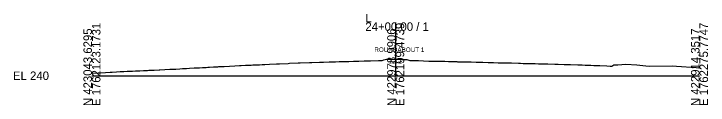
# Model space of a CAD drawing. Extents: x -26 to 3203, y -11010 to 4024.
# Drawn here: x -25.7 to 202.8, y -2009.7 to -1979.6 of the extents above; entities that cross this region are included whole.
import ezdxf

# ---------------------------------------------------------------- set-up
doc = ezdxf.new("R2010")
doc.units = 0
for name, color, linetype in [('Default', 7, 'Continuous'), ('Exist Cross Section Cell', 7, 'Continuous'), ('Exist XS Center Line Elevation Label', 7, 'Continuous'), ('Exist XS Ground Line', 7, 'Continuous'), ('Prop XS SE Text', 7, 'Continuous')]:
    doc.layers.add(name, color=color, linetype=linetype)

msp = doc.modelspace()

# ---------------------------------------------------------------- linework, layer by layer
at = {"layer": 'Exist Cross Section Cell'}
for p, q in [((100, -2000), (100, -1982.38)), ((0, -2000), (100, -2000)), ((100, -2000), (200, -2000))]:
    msp.add_line(p, q, dxfattribs=at)
at = {"layer": 'Exist XS Ground Line'}
msp.add_lwpolyline([(0, -1999.13), (2, -1999.02), (2.67, -1998.99), (2.8, -1998.98), (4.5, -1998.91), (5.96, -1998.82), (6.28, -1998.8), (6.67, -1998.78), (8.05, -1998.72), (9.24, -1998.64), (9.83, -1998.61), (10.53, -1998.57), (11.6, -1998.52), (12.5, -1998.47), (13.37, -1998.43), (14.39, -1998.38), (15.15, -1998.35), (15.79, -1998.32), (16.93, -1998.27), (18.27, -1998.21), (18.7, -1998.19), (19.07, -1998.17), (20.47, -1998.11), (22.14, -1998.02), (22.25, -1998.01), (22.34, -1998.01), (24.02, -1997.95), (25.62, -1997.87), (26.01, -1997.85), (27.57, -1997.77), (28.9, -1997.68), (29.86, -1997.63), (31.11, -1997.56), (32.17, -1997.51), (33.7, -1997.43), (34.65, -1997.38), (35.45, -1997.34), (36.42, -1997.29), (37.57, -1997.22), (38.2, -1997.19), (38.73, -1997.16), (39.97, -1997.09), (41.44, -1997), (41.75, -1996.99), (42.01, -1996.97), (43.52, -1996.89), (45.29, -1996.8), (45.29, -1996.8), (45.3, -1996.8), (47.07, -1996.71), (48.57, -1996.65), (49.16, -1996.62), (50.6, -1996.55), (51.88, -1996.49), (52.38, -1996.47), (52.99, -1996.44), (54.09, -1996.38), (55.16, -1996.34), (56, -1996.3), (56.94, -1996.25), (58.41, -1996.17), (60.78, -1996.07), (61.71, -1996.03), (64.63, -1995.9), (65.04, -1995.88), (67.9, -1995.75), (68.3, -1995.73), (68.43, -1995.72), (68.52, -1995.72), (71.61, -1995.63), (71.99, -1995.62), (72.42, -1995.6), (74.86, -1995.53), (75.52, -1995.51), (76.27, -1995.49), (78.09, -1995.45), (79.44, -1995.4), (79.92, -1995.38), (80, -1995.38), (80.22, -1995.37), (81.34, -1995.33), (82.54, -1995.3), (83.97, -1995.25), (84.61, -1995.24), (86.05, -1995.2), (87.82, -1995.17), (87.9, -1995.17), (89.57, -1995.13), (91.15, -1995.09), (91.67, -1995.08), (94.33, -1995.01), (95.09, -1994.97), (95.57, -1994.93), (96.07, -1994.8), (96.92, -1994.58), (98.21, -1994.57), (102.15, -1994.6), (103.49, -1994.62), (103.51, -1994.62), (103.67, -1994.67), (104.61, -1994.96), (104.7, -1994.96), (107.24, -1994.99), (107.52, -1995), (109.18, -1995.08), (110.93, -1995.14), (111, -1995.14), (111.09, -1995.14), (114, -1995.19), (114.92, -1995.21), (116.22, -1995.23), (117.34, -1995.27), (118.03, -1995.3), (118.8, -1995.31), (120.07, -1995.34), (120.39, -1995.35), (121.08, -1995.36), (122.64, -1995.39), (123.58, -1995.41), (124.72, -1995.43), (124.82, -1995.43), (126.5, -1995.47), (126.79, -1995.48), (127.06, -1995.49), (128.68, -1995.52), (130.4, -1995.57), (130.41, -1995.57), (132.2, -1995.63), (133.76, -1995.68), (134.02, -1995.69), (134.3, -1995.69), (135.78, -1995.73), (137.12, -1995.76), (137.6, -1995.77), (138.15, -1995.78), (140.42, -1995.85), (141.13, -1995.87), (141.99, -1995.9), (143.66, -1995.93), (144.66, -1995.95), (145.95, -1995.98), (146.99, -1996.01), (149.8, -1996.11), (149.94, -1996.11), (150.09, -1996.11), (152.4, -1996.18), (153.38, -1996.21), (153.44, -1996.21), (153.52, -1996.21), (155.46, -1996.26), (156.8, -1996.29), (157.5, -1996.31), (159.97, -1996.38), (160.59, -1996.4), (161.33, -1996.42), (162.41, -1996.46), (163.37, -1996.5), (164.21, -1996.53), (165.22, -1996.57), (166.46, -1996.62), (166.82, -1996.64), (167.2, -1996.65), (169.47, -1996.75), (170.65, -1996.8), (171.16, -1996.82), (171.51, -1996.58), (171.82, -1996.38), (172.05, -1996.38), (173.17, -1996.36), (175.79, -1996.19), (179.33, -1996.41), (182.34, -1996.74), (183.43, -1996.78), (191.26, -1996.72), (192.43, -1996.81), (198.92, -1997.29), (200, -1997.38)], dxfattribs=at)
msp.add_lwpolyline([(0, -1999.13), (2, -1999.02), (2.67, -1998.99), (2.8, -1998.98), (4.5, -1998.91), (5.96, -1998.82), (6.28, -1998.8), (6.67, -1998.78), (8.05, -1998.72), (9.24, -1998.64), (9.83, -1998.61), (10.53, -1998.57), (11.6, -1998.52), (12.5, -1998.47), (13.37, -1998.43), (14.39, -1998.38), (15.15, -1998.35), (15.79, -1998.32), (16.93, -1998.27), (18.27, -1998.21), (18.7, -1998.19), (19.07, -1998.17), (20.47, -1998.11), (22.14, -1998.02), (22.25, -1998.01), (22.34, -1998.01), (24.02, -1997.95), (25.62, -1997.87), (26.01, -1997.85), (27.57, -1997.77), (28.9, -1997.68), (29.86, -1997.63), (31.11, -1997.56), (32.17, -1997.51), (33.7, -1997.43), (34.65, -1997.38), (35.45, -1997.34), (36.42, -1997.29), (37.57, -1997.22), (38.2, -1997.19), (38.73, -1997.16), (39.97, -1997.09), (41.44, -1997), (41.75, -1996.99), (42.01, -1996.97), (43.52, -1996.89), (45.29, -1996.8), (45.29, -1996.8), (45.3, -1996.8), (47.07, -1996.71), (48.57, -1996.65), (49.16, -1996.62), (50.6, -1996.55), (51.88, -1996.49), (52.38, -1996.47), (52.99, -1996.44), (54.09, -1996.38), (55.16, -1996.34), (56, -1996.3), (56.94, -1996.25), (58.41, -1996.17), (60.78, -1996.07), (61.71, -1996.03), (64.63, -1995.9), (65.04, -1995.88), (67.9, -1995.75), (68.3, -1995.73), (68.43, -1995.72), (68.52, -1995.72), (71.61, -1995.63), (71.99, -1995.62), (72.42, -1995.6), (74.86, -1995.53), (75.52, -1995.51), (76.27, -1995.49), (78.09, -1995.45), (79.44, -1995.4), (79.92, -1995.38), (80, -1995.38), (80.22, -1995.37), (81.34, -1995.33), (82.54, -1995.3), (83.97, -1995.25), (84.61, -1995.24), (86.05, -1995.2), (87.82, -1995.17), (87.9, -1995.17), (89.57, -1995.13), (91.15, -1995.09), (91.67, -1995.08), (94.33, -1995.01), (95.09, -1994.97), (95.57, -1994.93), (96.07, -1994.8), (96.92, -1994.58), (98.21, -1994.57), (102.15, -1994.6), (103.49, -1994.62), (103.51, -1994.62), (103.67, -1994.67), (104.61, -1994.96), (104.7, -1994.96), (107.24, -1994.99), (107.52, -1995), (109.18, -1995.08), (110.93, -1995.14), (111, -1995.14), (111.09, -1995.14), (114, -1995.19), (114.92, -1995.21), (116.22, -1995.23), (117.34, -1995.27), (118.03, -1995.3), (118.8, -1995.31), (120.07, -1995.34), (120.39, -1995.35), (121.08, -1995.36), (122.64, -1995.39), (123.58, -1995.41), (124.72, -1995.43), (124.82, -1995.43), (126.5, -1995.47), (126.79, -1995.48), (127.06, -1995.49), (128.68, -1995.52), (130.4, -1995.57), (130.41, -1995.57), (132.2, -1995.63), (133.76, -1995.68), (134.02, -1995.69), (134.3, -1995.69), (135.78, -1995.73), (137.12, -1995.76), (137.6, -1995.77), (138.15, -1995.78), (140.42, -1995.85), (141.13, -1995.87), (141.99, -1995.9), (143.66, -1995.93), (144.66, -1995.95), (145.95, -1995.98), (146.99, -1996.01), (149.8, -1996.11), (149.94, -1996.11), (150.09, -1996.11), (152.4, -1996.18), (153.38, -1996.21), (153.44, -1996.21), (153.52, -1996.21), (155.46, -1996.26), (156.8, -1996.29), (157.5, -1996.31), (159.97, -1996.38), (160.59, -1996.4), (161.33, -1996.42), (162.41, -1996.46), (163.37, -1996.5), (164.21, -1996.53), (165.22, -1996.57), (166.46, -1996.62), (166.82, -1996.64), (167.2, -1996.65), (169.47, -1996.75), (170.65, -1996.8), (171.16, -1996.82), (171.51, -1996.58), (171.82, -1996.38), (172.05, -1996.38), (173.17, -1996.36), (175.79, -1996.19), (179.33, -1996.41), (182.34, -1996.74), (183.43, -1996.78), (191.26, -1996.72), (192.43, -1996.81), (198.92, -1997.29), (200, -1997.38)], dxfattribs=at)
msp.add_lwpolyline([(0, -1999.13), (2, -1999.02), (2.67, -1998.99), (2.8, -1998.98), (4.5, -1998.91), (5.96, -1998.82), (6.28, -1998.8), (6.67, -1998.78), (8.05, -1998.72), (9.24, -1998.64), (9.83, -1998.61), (10.53, -1998.57), (11.6, -1998.52), (12.5, -1998.47), (13.37, -1998.43), (14.39, -1998.38), (15.15, -1998.35), (15.79, -1998.32), (16.93, -1998.27), (18.27, -1998.21), (18.7, -1998.19), (19.07, -1998.17), (20.47, -1998.11), (22.14, -1998.02), (22.25, -1998.01), (22.34, -1998.01), (24.02, -1997.95), (25.62, -1997.87), (26.01, -1997.85), (27.57, -1997.77), (28.9, -1997.68), (29.86, -1997.63), (31.11, -1997.56), (32.17, -1997.51), (33.7, -1997.43), (34.65, -1997.38), (35.45, -1997.34), (36.42, -1997.29), (37.57, -1997.22), (38.2, -1997.19), (38.73, -1997.16), (39.97, -1997.09), (41.44, -1997), (41.75, -1996.99), (42.01, -1996.97), (43.52, -1996.89), (45.29, -1996.8), (45.29, -1996.8), (45.3, -1996.8), (47.07, -1996.71), (48.57, -1996.65), (49.16, -1996.62), (50.6, -1996.55), (51.88, -1996.49), (52.38, -1996.47), (52.99, -1996.44), (54.09, -1996.38), (55.16, -1996.34), (56, -1996.3), (56.94, -1996.25), (58.41, -1996.17), (60.78, -1996.07), (61.71, -1996.03), (64.63, -1995.9), (65.04, -1995.88), (67.9, -1995.75), (68.3, -1995.73), (68.43, -1995.72), (68.52, -1995.72), (71.61, -1995.63), (71.99, -1995.62), (72.42, -1995.6), (74.86, -1995.53), (75.52, -1995.51), (76.27, -1995.49), (78.09, -1995.45), (79.44, -1995.4), (79.92, -1995.38), (80, -1995.38), (80.22, -1995.37), (81.34, -1995.33), (82.54, -1995.3), (83.97, -1995.25), (84.61, -1995.24), (86.05, -1995.2), (87.82, -1995.17), (87.9, -1995.17), (89.57, -1995.13), (91.15, -1995.09), (91.67, -1995.08), (94.33, -1995.01), (95.09, -1994.97), (95.57, -1994.93), (96.07, -1994.8), (96.92, -1994.58), (98.21, -1994.57), (102.15, -1994.6), (103.49, -1994.62), (103.51, -1994.62), (103.67, -1994.67), (104.61, -1994.96), (104.7, -1994.96), (107.24, -1994.99), (107.52, -1995), (109.18, -1995.08), (110.93, -1995.14), (111, -1995.14), (111.09, -1995.14), (114, -1995.19), (114.92, -1995.21), (116.22, -1995.23), (117.34, -1995.27), (118.03, -1995.3), (118.8, -1995.31), (120.07, -1995.34), (120.39, -1995.35), (121.08, -1995.36), (122.64, -1995.39), (123.58, -1995.41), (124.72, -1995.43), (124.82, -1995.43), (126.5, -1995.47), (126.79, -1995.48), (127.06, -1995.49), (128.68, -1995.52), (130.4, -1995.57), (130.41, -1995.57), (132.2, -1995.63), (133.76, -1995.68), (134.02, -1995.69), (134.3, -1995.69), (135.78, -1995.73), (137.12, -1995.76), (137.6, -1995.77), (138.15, -1995.78), (140.42, -1995.85), (141.13, -1995.87), (141.99, -1995.9), (143.66, -1995.93), (144.66, -1995.95), (145.95, -1995.98), (146.99, -1996.01), (149.8, -1996.11), (149.94, -1996.11), (150.09, -1996.11), (152.4, -1996.18), (153.38, -1996.21), (153.44, -1996.21), (153.52, -1996.21), (155.46, -1996.26), (156.8, -1996.29), (157.5, -1996.31), (159.97, -1996.38), (160.59, -1996.4), (161.33, -1996.42), (162.41, -1996.46), (163.37, -1996.5), (164.21, -1996.53), (165.22, -1996.57), (166.46, -1996.62), (166.82, -1996.64), (167.2, -1996.65), (169.47, -1996.75), (170.65, -1996.8), (171.16, -1996.82), (171.51, -1996.58), (171.82, -1996.38), (172.05, -1996.38), (173.17, -1996.36), (175.79, -1996.19), (179.33, -1996.41), (182.34, -1996.74), (183.43, -1996.78), (191.26, -1996.72), (192.43, -1996.81), (198.92, -1997.29), (200, -1997.38)], dxfattribs=at)
msp.add_lwpolyline([(0, -1999.13), (2, -1999.02), (2.67, -1998.99), (2.8, -1998.98), (4.5, -1998.91), (5.96, -1998.82), (6.28, -1998.8), (6.67, -1998.78), (8.05, -1998.72), (9.24, -1998.64), (9.83, -1998.61), (10.53, -1998.57), (11.6, -1998.52), (12.5, -1998.47), (13.37, -1998.43), (14.39, -1998.38), (15.15, -1998.35), (15.79, -1998.32), (16.93, -1998.27), (18.27, -1998.21), (18.7, -1998.19), (19.07, -1998.17), (20.47, -1998.11), (22.14, -1998.02), (22.25, -1998.01), (22.34, -1998.01), (24.02, -1997.95), (25.62, -1997.87), (26.01, -1997.85), (27.57, -1997.77), (28.9, -1997.68), (29.86, -1997.63), (31.11, -1997.56), (32.17, -1997.51), (33.7, -1997.43), (34.65, -1997.38), (35.45, -1997.34), (36.42, -1997.29), (37.57, -1997.22), (38.2, -1997.19), (38.73, -1997.16), (39.97, -1997.09), (41.44, -1997), (41.75, -1996.99), (42.01, -1996.97), (43.52, -1996.89), (45.29, -1996.8), (45.29, -1996.8), (45.3, -1996.8), (47.07, -1996.71), (48.57, -1996.65), (49.16, -1996.62), (50.6, -1996.55), (51.88, -1996.49), (52.38, -1996.47), (52.99, -1996.44), (54.09, -1996.38), (55.16, -1996.34), (56, -1996.3), (56.94, -1996.25), (58.41, -1996.17), (60.78, -1996.07), (61.71, -1996.03), (64.63, -1995.9), (65.04, -1995.88), (67.9, -1995.75), (68.3, -1995.73), (68.43, -1995.72), (68.52, -1995.72), (71.61, -1995.63), (71.99, -1995.62), (72.42, -1995.6), (74.86, -1995.53), (75.52, -1995.51), (76.27, -1995.49), (78.09, -1995.45), (79.44, -1995.4), (79.92, -1995.38), (80, -1995.38), (80.22, -1995.37), (81.34, -1995.33), (82.54, -1995.3), (83.97, -1995.25), (84.61, -1995.24), (86.05, -1995.2), (87.82, -1995.17), (87.9, -1995.17), (89.57, -1995.13), (91.15, -1995.09), (91.67, -1995.08), (94.33, -1995.01), (95.09, -1994.97), (95.57, -1994.93), (96.07, -1994.8), (96.92, -1994.58), (98.21, -1994.57), (102.15, -1994.6), (103.49, -1994.62), (103.51, -1994.62), (103.67, -1994.67), (104.61, -1994.96), (104.7, -1994.96), (107.24, -1994.99), (107.52, -1995), (109.18, -1995.08), (110.93, -1995.14), (111, -1995.14), (111.09, -1995.14), (114, -1995.19), (114.92, -1995.21), (116.22, -1995.23), (117.34, -1995.27), (118.03, -1995.3), (118.8, -1995.31), (120.07, -1995.34), (120.39, -1995.35), (121.08, -1995.36), (122.64, -1995.39), (123.58, -1995.41), (124.72, -1995.43), (124.82, -1995.43), (126.5, -1995.47), (126.79, -1995.48), (127.06, -1995.49), (128.68, -1995.52), (130.4, -1995.57), (130.41, -1995.57), (132.2, -1995.63), (133.76, -1995.68), (134.02, -1995.69), (134.3, -1995.69), (135.78, -1995.73), (137.12, -1995.76), (137.6, -1995.77), (138.15, -1995.78), (140.42, -1995.85), (141.13, -1995.87), (141.99, -1995.9), (143.66, -1995.93), (144.66, -1995.95), (145.95, -1995.98), (146.99, -1996.01), (149.8, -1996.11), (149.94, -1996.11), (150.09, -1996.11), (152.4, -1996.18), (153.38, -1996.21), (153.44, -1996.21), (153.52, -1996.21), (155.46, -1996.26), (156.8, -1996.29), (157.5, -1996.31), (159.97, -1996.38), (160.59, -1996.4), (161.33, -1996.42), (162.41, -1996.46), (163.37, -1996.5), (164.21, -1996.53), (165.22, -1996.57), (166.46, -1996.62), (166.82, -1996.64), (167.2, -1996.65), (169.47, -1996.75), (170.65, -1996.8), (171.16, -1996.82), (171.51, -1996.58), (171.82, -1996.38), (172.05, -1996.38), (173.17, -1996.36), (175.79, -1996.19), (179.33, -1996.41), (182.34, -1996.74), (183.43, -1996.78), (191.26, -1996.72), (192.43, -1996.81), (198.92, -1997.29), (200, -1997.38)], dxfattribs=at)
msp.add_lwpolyline([(0, -1999.13), (2, -1999.02), (2.67, -1998.99), (2.8, -1998.98), (4.5, -1998.91), (5.96, -1998.82), (6.28, -1998.8), (6.67, -1998.78), (8.05, -1998.72), (9.24, -1998.64), (9.83, -1998.61), (10.53, -1998.57), (11.6, -1998.52), (12.5, -1998.47), (13.37, -1998.43), (14.39, -1998.38), (15.15, -1998.35), (15.79, -1998.32), (16.93, -1998.27), (18.27, -1998.21), (18.7, -1998.19), (19.07, -1998.17), (20.47, -1998.11), (22.14, -1998.02), (22.25, -1998.01), (22.34, -1998.01), (24.02, -1997.95), (25.62, -1997.87), (26.01, -1997.85), (27.57, -1997.77), (28.9, -1997.68), (29.86, -1997.63), (31.11, -1997.56), (32.17, -1997.51), (33.7, -1997.43), (34.65, -1997.38), (35.45, -1997.34), (36.42, -1997.29), (37.57, -1997.22), (38.2, -1997.19), (38.73, -1997.16), (39.97, -1997.09), (41.44, -1997), (41.75, -1996.99), (42.01, -1996.97), (43.52, -1996.89), (45.29, -1996.8), (45.29, -1996.8), (45.3, -1996.8), (47.07, -1996.71), (48.57, -1996.65), (49.16, -1996.62), (50.6, -1996.55), (51.88, -1996.49), (52.38, -1996.47), (52.99, -1996.44), (54.09, -1996.38), (55.16, -1996.34), (56, -1996.3), (56.94, -1996.25), (58.41, -1996.17), (60.78, -1996.07), (61.71, -1996.03), (64.63, -1995.9), (65.04, -1995.88), (67.9, -1995.75), (68.3, -1995.73), (68.43, -1995.72), (68.52, -1995.72), (71.61, -1995.63), (71.99, -1995.62), (72.42, -1995.6), (74.86, -1995.53), (75.52, -1995.51), (76.27, -1995.49), (78.09, -1995.45), (79.44, -1995.4), (79.92, -1995.38), (80, -1995.38), (80.22, -1995.37), (81.34, -1995.33), (82.54, -1995.3), (83.97, -1995.25), (84.61, -1995.24), (86.05, -1995.2), (87.82, -1995.17), (87.9, -1995.17), (89.57, -1995.13), (91.15, -1995.09), (91.67, -1995.08), (94.33, -1995.01), (95.09, -1994.97), (95.57, -1994.93), (96.07, -1994.8), (96.92, -1994.58), (98.21, -1994.57), (102.15, -1994.6), (103.49, -1994.62), (103.51, -1994.62), (103.67, -1994.67), (104.61, -1994.96), (104.7, -1994.96), (107.24, -1994.99), (107.52, -1995), (109.18, -1995.08), (110.93, -1995.14), (111, -1995.14), (111.09, -1995.14), (114, -1995.19), (114.92, -1995.21), (116.22, -1995.23), (117.34, -1995.27), (118.03, -1995.3), (118.8, -1995.31), (120.07, -1995.34), (120.39, -1995.35), (121.08, -1995.36), (122.64, -1995.39), (123.58, -1995.41), (124.72, -1995.43), (124.82, -1995.43), (126.5, -1995.47), (126.79, -1995.48), (127.06, -1995.49), (128.68, -1995.52), (130.4, -1995.57), (130.41, -1995.57), (132.2, -1995.63), (133.76, -1995.68), (134.02, -1995.69), (134.3, -1995.69), (135.78, -1995.73), (137.12, -1995.76), (137.6, -1995.77), (138.15, -1995.78), (140.42, -1995.85), (141.13, -1995.87), (141.99, -1995.9), (143.66, -1995.93), (144.66, -1995.95), (145.95, -1995.98), (146.99, -1996.01), (149.8, -1996.11), (149.94, -1996.11), (150.09, -1996.11), (152.4, -1996.18), (153.38, -1996.21), (153.44, -1996.21), (153.52, -1996.21), (155.46, -1996.26), (156.8, -1996.29), (157.5, -1996.31), (159.97, -1996.38), (160.59, -1996.4), (161.33, -1996.42), (162.41, -1996.46), (163.37, -1996.5), (164.21, -1996.53), (165.22, -1996.57), (166.46, -1996.62), (166.82, -1996.64), (167.2, -1996.65), (169.47, -1996.75), (170.65, -1996.8), (171.16, -1996.82), (171.51, -1996.58), (171.82, -1996.38), (172.05, -1996.38), (173.17, -1996.36), (175.79, -1996.19), (179.33, -1996.41), (182.34, -1996.74), (183.43, -1996.78), (191.26, -1996.72), (192.43, -1996.81), (198.92, -1997.29), (200, -1997.38)], dxfattribs=at)

# ---------------------------------------------------------------- texts
at = {"layer": 'Default'}
msp.add_text('-', height=0.0001, dxfattribs=at).set_placement((0, -2000))
at = {"layer": 'Exist Cross Section Cell'}
for s, p in [('L', (90, -1982.38)), ('24+00.00 / 1', (90, -1985.18)), ('EL 240', (-26, -2001.4))]:
    msp.add_text(s, height=2.8, dxfattribs=at).set_placement(p)
for s, p in [('E 1762123.1731', (2.8, -2010)), ('E 1762199.4739', (102.8, -2010)), ('E 1762275.7747', (202.8, -2010)), ('N 423043.6295', (0, -2010)), ('N 422978.9906', (100, -2010)), ('N 422914.3517', (200, -2010))]:
    msp.add_text(s, height=2.8, rotation=90, dxfattribs=at).set_placement(p)
at = {"layer": 'Exist XS Center Line Elevation Label'}
msp.add_text('245.42', height=1, dxfattribs=at).set_placement((97.89, -1996.08))
at = {"layer": 'Prop XS SE Text'}
msp.add_text('ROUNDABOUT 1', height=1.5, rotation=360, dxfattribs=at).set_placement((92.97, -1992.15))

doc.saveas('drawing.dxf')
